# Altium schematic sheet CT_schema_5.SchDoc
size 226 x 144 mm
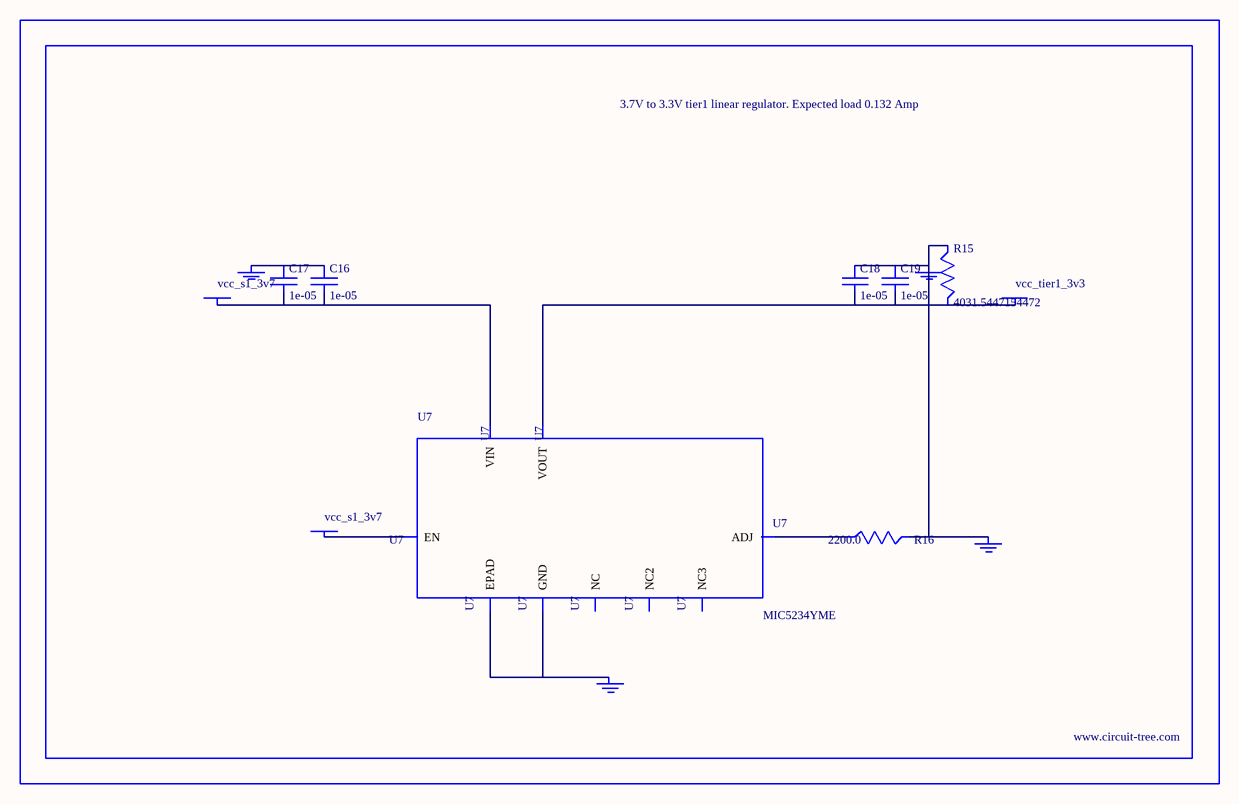
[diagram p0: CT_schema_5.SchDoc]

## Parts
BORDER4  (no value)
C16  1e-05  [C1210]
C17  1e-05  [C1210]
C18  1e-05  [C1210]
C19  1e-05  [C1210]
GND_INSTANCE_4_0  (no value)
GND_INSTANCE_4_1  (no value)
GND_INSTANCE_4_2  (no value)
GND_INSTANCE_4_3  (no value)
POWER_INSTANCE_4_0  vcc_tier1_3v3
POWER_INSTANCE_4_1  vcc_s1_3v7
POWER_INSTANCE_4_2  vcc_s1_3v7
R15  4031.5447154472  [R0603]
R16  2200.0  [R0603]
U7  MIC5234YME  [SOIC-8_EP]

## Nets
NetC16_1: C16.1 C17.1 GND_INSTANCE_4_3.0(GND)
NetC16_2: C16.2 C17.2 POWER_INSTANCE_4_2.0(PWR) U7.8(VIN)
NetC18_1: C18.1 C19.1 GND_INSTANCE_4_0.0(GND) GND_INSTANCE_4_1.0(GND) R15.1 R16.2
NetC18_2: C18.2 C19.2 POWER_INSTANCE_4_0.0(PWR) R15.2 U7.1(VOUT)
NetGND_INSTANCE_4_2_0: GND_INSTANCE_4_2.0(GND) U7.7(GND) U7.EPAD
NetPOWER_INSTANCE_4_1_0: POWER_INSTANCE_4_1.0(PWR) U7.5(EN)
NetR16_1: R16.1 U7.4(ADJ)

Not connected (* = marked no-connect by the designer): U7 2(NC) 3(NC2) 6(NC3)

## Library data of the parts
BORDER4 = BORDER_PAGE4
C16-C19 = C1210C106K5PACTU
GND_INSTANCE_4_0-GND_INSTANCE_4_3 = GND
POWER_INSTANCE_4_0-POWER_INSTANCE_4_2 = PWR
R15 = R15
R16 = RC0603JR-072K2L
